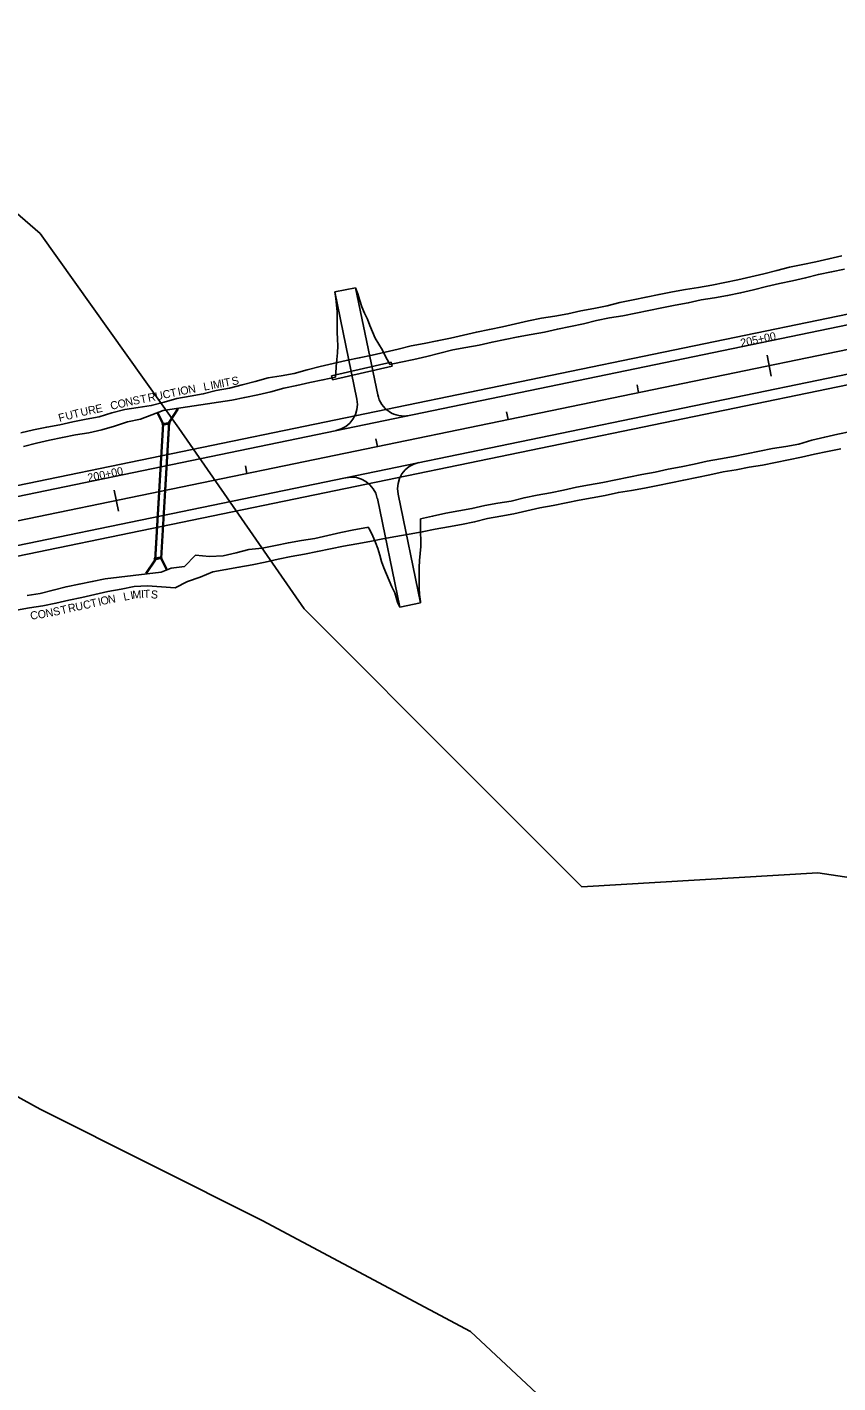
# Model space of a CAD drawing. Extents: x 979959 to 994833, y 1835619 to 1845316.
# Drawn here: x 985720 to 986328, y 1837353 to 1838370 of the extents above; entities that cross this region are included whole.
import ezdxf

# ---------------------------------------------------------------- set-up
doc = ezdxf.new("R2010")
doc.units = 0
for name, color, linetype in [('43', 7, 'Continuous'), ('Future 5 Lane Construction Limits', 7, 'Continuous'), ('R_Drainage', 7, 'Continuous'), ('R_Horz Alg', 7, 'Continuous'), ('R_Horz Alg Stationing', 7, 'Continuous'), ('R_Proposed Const Limits', 7, 'Continuous'), ('R_Proposed Road', 7, 'Continuous')]:
    doc.layers.add(name, color=color, linetype=linetype)

msp = doc.modelspace()

# ---------------------------------------------------------------- linework, layer by layer
at = {"layer": '43'}
for points in [[(985647.3, 1838286.1), (985729.8, 1838214.9), (985834, 1838069.1), (985927.8, 1837933.7), (986052.8, 1837808.6), (986136.1, 1837725.3), (986313.2, 1837735.7), (986521.5, 1837704.5)], [(986209, 1837246.1), (986052.8, 1837391.9), (985896.5, 1837475.2), (985729.8, 1837558.6), (985521.5, 1837673.2)]]:
    msp.add_lwpolyline(points, dxfattribs=at)
at = {"layer": 'Future 5 Lane Construction Limits'}
for points in [[(985715.3, 1838065.5), (985725, 1838067.8), (985734.8, 1838069.8), (985744.7, 1838071.6), (985754.5, 1838073.7), (985764.3, 1838075.7), (985774.1, 1838077.4), (985783.7, 1838080.5), (985793.4, 1838083), (985803.3, 1838084.5), (985813.2, 1838085.9), (985822.9, 1838088.6), (985832.5, 1838091.2), (985842.4, 1838093), (985852.2, 1838094.7), (985861.9, 1838097.2), (985871.8, 1838099), (985881.5, 1838101.4), (985891.1, 1838104.1), (985900.8, 1838106.7), (985910.7, 1838108.3), (985920.5, 1838110.1), (985930.2, 1838112.8), (985939.9, 1838115.2), (985949.6, 1838117.4), (985959.4, 1838119.7), (985969.2, 1838121.7), (985979, 1838123.8), (985988.7, 1838126.1), (985998.5, 1838128.3), (986008.2, 1838130.7), (986018, 1838132.5), (986027.8, 1838134.4), (986037.6, 1838136.5), (986047.4, 1838138.7), (986057.1, 1838141), (986066.9, 1838143.1), (986076.7, 1838145.1), (986086.4, 1838147.2), (986096.2, 1838149.5), (986106, 1838151.4), (986115.9, 1838153), (986125.8, 1838154.7), (986135.5, 1838156.9), (986145.3, 1838158.8), (986155.1, 1838160.8), (986164.8, 1838163.2), (986174.6, 1838165.2), (986184.4, 1838167.3), (986194.2, 1838169.3), (986204.1, 1838171.1), (986213.9, 1838172.9), (986223.8, 1838174.5), (986233.6, 1838176.3), (986243.4, 1838178.1), (986253.2, 1838180.3), (986263, 1838182.5), (986272.7, 1838184.6), (986282.4, 1838187.1), (986292.1, 1838189.6), (986301.9, 1838191.7), (986311.7, 1838193.8), (986321.5, 1838195.9), (986331.2, 1838198.1)], [(985712.1, 1837932.7), (985722, 1837934.3), (985731.9, 1837935.9), (985741.7, 1837937.8), (985751.4, 1837940.1), (985761.2, 1837942.1), (985770.9, 1837944.4), (985780.7, 1837946.7), (985790.6, 1837948.3), (985800.4, 1837950.3), (985810.5, 1837950.8), (985820.8, 1837950), (985831.2, 1837949.4), (985840.4, 1837954), (985849.9, 1837957.4), (985859.4, 1837961.3), (985869.2, 1837963), (985879, 1837964.8), (985888.9, 1837966.7), (985898.7, 1837968.6), (985908.4, 1837970.8), (985918.2, 1837972.8), (985928.1, 1837974.7), (985937.9, 1837976.7), (985947.7, 1837978.6), (985957.5, 1837980.5), (985967.3, 1837982.3), (985977.2, 1837984.1), (985987, 1837986), (985996.8, 1837987.8), (986006.7, 1837989.6), (986016.5, 1837991.3), (986026.3, 1837993.3), (986036.2, 1837995.1), (986046, 1837996.9), (986055.8, 1837998.8), (986065.5, 1838001.2), (986075.4, 1838003), (986085.2, 1838004.9), (986095, 1838007.1), (986104.7, 1838009.2), (986114.6, 1838011), (986124.4, 1838013), (986134.2, 1838015), (986144, 1838016.8), (986153.8, 1838018.6), (986163.6, 1838020.8), (986173.5, 1838022.4), (986183.3, 1838024.1), (986193.2, 1838026.1), (986203, 1838028.1), (986212.7, 1838030.1), (986222.5, 1838032.1), (986232.3, 1838034.1), (986242.1, 1838036.2), (986252, 1838037.9), (986261.8, 1838039.8), (986271.7, 1838041.3), (986281.5, 1838043.3), (986291.3, 1838045.3), (986301.1, 1838047.4), (986310.8, 1838049.5), (986320.6, 1838051.6), (986330.4, 1838053.6)]]:
    msp.add_lwpolyline(points, dxfattribs=at)
at = {"layer": 'R_Drainage'}
for p, q in [((985948.4, 1838108.2), (985993.3, 1838118.4)), ((985949.1, 1838105.2), (985993.9, 1838115.5)), ((985993.3, 1838118.4), (985993.9, 1838115.5)), ((985948.4, 1838108.2), (985949.1, 1838105.2)), ((985826.3, 1838073.4), (985833, 1838083.6)), ((985826.8, 1838073.3), (985833.4, 1838083.3)), ((985833.4, 1838083.3), (985833, 1838083.6)), ((985821.8, 1838072.2), (985815.8, 1837970.4)), ((985822.3, 1838072.3), (985816.3, 1837970.2)), ((985817.8, 1838080.1), (985818.3, 1838080.3)), ((985821.8, 1838072.2), (985817.8, 1838080.1)), ((985822.3, 1838072.3), (985818.3, 1838080.3)), ((985826.3, 1838073.4), (985820.4, 1837971.4)), ((985826.8, 1838073.3), (985820.9, 1837971.5)), ((985821.5, 1838072.2), (985827.1, 1838073.3)), ((985821.7, 1838071.2), (985821.5, 1838072.2)), ((985821.7, 1838071.2), (985827.3, 1838072.4)), ((985821.7, 1838071.2), (985826.8, 1838072.3)), ((985827.3, 1838072.4), (985827.1, 1838073.3)), ((985815.8, 1837970.4), (985809.2, 1837960.4)), ((985816.3, 1837970.2), (985809.6, 1837960.1)), ((985815.4, 1837971.3), (985821, 1837972.5)), ((985815.4, 1837971.3), (985820.4, 1837972.4)), ((985815.6, 1837970.4), (985815.4, 1837971.3)), ((985815.6, 1837970.4), (985821.2, 1837971.5)), ((985820.4, 1837971.4), (985824.4, 1837963.4)), ((985820.9, 1837971.5), (985824.8, 1837963.6)), ((985821.2, 1837971.5), (985821, 1837972.5)), ((985809.2, 1837960.4), (985809.6, 1837960.1)), ((985824.8, 1837963.6), (985824.4, 1837963.4))]:
    msp.add_line(p, q, dxfattribs=at)
at = {"layer": 'R_Horz Alg'}
msp.add_line((984572.5, 1837764), (990033.8, 1838891.5), dxfattribs=at)
at = {"layer": 'R_Horz Alg Stationing'}
for points in [[(986275.1, 1838123.7), (986278.3, 1838108)], [(986177.6, 1838101.5), (986178.8, 1838095.6)], [(986079.6, 1838081.3), (986080.9, 1838075.4)], [(985981.7, 1838061.1), (985982.9, 1838055.2)], [(985883.8, 1838040.9), (985885, 1838035)], [(985785.4, 1838022.6), (985788.7, 1838006.9)]]:
    msp.add_lwpolyline(points, dxfattribs=at)
at = {"layer": 'R_Proposed Const Limits'}
for points in [[(985992.2, 1838116.7), (986000.5, 1838118.5), (986010.3, 1838120.5), (986020, 1838122.8), (986029.7, 1838125.3), (986039.4, 1838127.7), (986049.2, 1838129.6), (986059.1, 1838131.3), (986068.9, 1838133.5), (986078.6, 1838135.6), (986088.5, 1838137.4), (986098.3, 1838139.3), (986108.1, 1838141.1), (986117.9, 1838143.3), (986127.7, 1838145.3), (986137.5, 1838147.3), (986147.2, 1838149.6), (986157, 1838151.6), (986166.9, 1838153.3), (986176.7, 1838155.3), (986186.5, 1838157.3), (986196.3, 1838159.3), (986206.1, 1838161.1), (986216, 1838162.9), (986225.7, 1838165.1), (986235.6, 1838166.7), (986245.5, 1838168.4), (986255.3, 1838170.4), (986265, 1838172.8), (986274.7, 1838175.1), (986284.4, 1838177.4), (986294.2, 1838179.5), (986304, 1838181.7), (986313.7, 1838184.3), (986323.5, 1838186.1), (986333.2, 1838188.3)], [(985992.2, 1838116.7), (985991.4, 1838118.2), (985989, 1838122.8), (985986.6, 1838127.4), (985983.8, 1838132), (985981.2, 1838136.5), (985979.1, 1838141.2), (985977.2, 1838145.9), (985975.3, 1838150.6), (985973.2, 1838155.3), (985971.2, 1838160), (985969.7, 1838164.8), (985968.2, 1838169.6), (985966.5, 1838174.3)], [(985951.5, 1838107.3), (985951.7, 1838110), (985951.9, 1838115.2), (985952.4, 1838120.4), (985952.8, 1838125.6), (985953.1, 1838130.7), (985952.9, 1838135.8), (985952.7, 1838140.9), (985952.6, 1838145.9), (985952.7, 1838151.1), (985952.7, 1838156.2), (985952.2, 1838161.2), (985951.6, 1838166.2), (985950.8, 1838171.1)], [(985717.4, 1838055.3), (985727.1, 1838057.7), (985736.9, 1838060), (985746.6, 1838062.1), (985756.5, 1838064), (985766.3, 1838065.6), (985776.1, 1838067.8), (985785.7, 1838070.6), (985795.3, 1838073.7), (985805.1, 1838075.8), (985822.1, 1838082.2), (985873.6, 1838089.9), (985883.4, 1838092.1), (985893.2, 1838094.1), (985903, 1838096.3), (985912.6, 1838098.9), (985922.4, 1838101.1), (985932.2, 1838103.2), (985942, 1838105.2), (985951.5, 1838107.3)], [(986015.2, 1838001.1), (986024.3, 1838003), (986034.1, 1838005.3), (986043.9, 1838007), (986053.8, 1838008.8), (986063.5, 1838011.1), (986073.3, 1838012.9), (986083.2, 1838014.4), (986092.9, 1838016.9), (986102.8, 1838018.8), (986112.6, 1838020.6), (986122.4, 1838022.5), (986132.2, 1838024.7), (986142, 1838026.6), (986151.9, 1838028.2), (986161.7, 1838030.2), (986171.5, 1838032.2), (986181.3, 1838034.2), (986191.1, 1838036.1), (986200.9, 1838038.2), (986210.7, 1838040.1), (986220.5, 1838042.1), (986230.3, 1838044.2), (986240.1, 1838046), (986249.9, 1838047.9), (986259.7, 1838049.8), (986269.5, 1838051.9), (986279.3, 1838053.9), (986289.2, 1838055.2), (986299.1, 1838057.1), (986308.7, 1838060), (986318.4, 1838062.3), (986328.2, 1838064.4), (986338, 1838066.4)], [(986015.2, 1838001.1), (986015.2, 1838000.6), (986015.2, 1837995.5), (986015.3, 1837990.4), (986015.4, 1837985.3), (986015.4, 1837980.2), (986014.9, 1837975), (986014.4, 1837969.8), (986014.3, 1837964.7), (986014.3, 1837959.6), (986014.2, 1837954.5), (986014.2, 1837949.3), (986014.5, 1837944.3), (986015.3, 1837939.1), (986015.3, 1837938)], [(985828.2, 1837964), (985838.1, 1837965.4), (985846.5, 1837973.8), (985857, 1837972.8), (985867.1, 1837973.3), (985876.8, 1837975.7), (985886.5, 1837978), (985896.5, 1837979.1), (985906.3, 1837981.1), (985916.1, 1837983.1), (985926, 1837984.9), (985935.9, 1837986.4), (985945.6, 1837988.5), (985955.4, 1837990.7), (985965.2, 1837992.7), (985975, 1837994.5), (985976, 1837994.7)], [(985976, 1837994.7), (985977.1, 1837992.7), (985979.4, 1837988.1), (985981.3, 1837983.4), (985983.1, 1837978.7), (985984.6, 1837973.9), (985986, 1837969.1), (985987.6, 1837964.3), (985989.6, 1837959.6), (985991.7, 1837954.9), (985993.8, 1837950.2), (985996, 1837945.6), (985997.9, 1837938.7), (985999.6, 1837934.9)], [(985778.7, 1837956.2), (985820.7, 1837961), (985828.2, 1837964)], [(985720.1, 1837943.5), (985729.9, 1837945.2), (985739.6, 1837947.7), (985749.3, 1837950.1), (985759.1, 1837952.1), (985769, 1837954), (985778.7, 1837956.2)]]:
    msp.add_lwpolyline(points, dxfattribs=at)
at = {"layer": 'R_Proposed Road'}
for p, q in [((984567.2, 1837789.5), (990028.6, 1838916.9)), ((984568.8, 1837781.7), (990030.2, 1838909.1)), ((984576.1, 1837746.4), (990037.5, 1838873.9)), ((984577.7, 1837738.6), (990039.1, 1838866)), ((985950.8, 1838171.1), (985966.5, 1838174.3)), ((985983.1, 1838094), (985966.5, 1838174.3)), ((985967.4, 1838090.8), (985950.8, 1838171.1)), ((985999.6, 1837934.9), (985982.8, 1838016.4)), ((986015.3, 1837938), (985998.4, 1838019.6)), ((985999.6, 1837934.9), (986015.3, 1837938))]:
    msp.add_line(p, q, dxfattribs=at)
for centre, start, end in [((986002.7, 1838098.1), 191.6644, 281.6644), ((985947.8, 1838086.8), 281.6644, 11.6644), ((986018, 1838023.7), 101.6644, 191.6644), ((985963.2, 1838012.3), 11.6644, 101.6644)]:
    msp.add_arc(centre, 20, start, end, dxfattribs=at)

# ---------------------------------------------------------------- texts
at = {"layer": 'Future 5 Lane Construction Limits'}
for s, rotation, p in [('N', 10.5552, (985841.4, 1838094.9)), ('L', 10.5552, (985852.9, 1838097.1)), ('I', 10.8926, (985858.2, 1838098)), ('M', 10.8926, (985860.1, 1838098.4)), ('I', 10.9749, (985866.4, 1838099.6)), ('T', 10.8302, (985868.4, 1838100)), ('S', 10.8302, (985874.1, 1838101.1)), ('N', 12.562, (985794.4, 1838085.2)), ('S', 11.4626, (985799.9, 1838086.4)), ('T', 11.4626, (985805.5, 1838087.5)), ('R', 11.4198, (985811.2, 1838088.7)), ('U', 11.4198, (985816.8, 1838089.8)), ('C', 11.471, (985822.4, 1838091)), ('T', 12.2203, (985828, 1838092.1)), ('I', 12.2203, (985833.7, 1838093.3)), ('O', 12.2203, (985835.7, 1838093.7)), ('U', 14.2158, (985749.6, 1838075)), ('T', 14.2158, (985755.2, 1838076.4)), ('U', 12.2951, (985760.8, 1838077.9)), ('R', 12.2951, (985766.5, 1838079.1)), ('E', 11.9819, (985772, 1838080.3)), ('C', 12.3558, (985783.2, 1838082.7)), ('O', 12.562, (985788.7, 1838083.9)), ('F', 14.5611, (985744.4, 1838073.6)), ('U', 11.4216, (985756.9, 1837932)), ('C', 13.3007, (985762.8, 1837933.2)), ('T', 13.3007, (985768.3, 1837934.5)), ('I', 13.222, (985774, 1837935.8)), ('O', 13.222, (985775.9, 1837936.3)), ('N', 9.4839, (985781.2, 1837937.6)), ('L', 11.5869, (985792.9, 1837939.6)), ('I', 11.5869, (985798.2, 1837940.7)), ('M', 3.0261, (985799.2, 1837941.2)), ('I', 3.0261, (985805.7, 1837941.6)), ('T', 3.0261, (985807.6, 1837941.7)), ('S', 355.3062, (985812.7, 1837941.6)), ('C', 8.6808, (985722.9, 1837925.4)), ('O', 8.6808, (985728.5, 1837926.2)), ('N', 10.94, (985734.5, 1837927.2)), ('S', 10.94, (985740.1, 1837928.3)), ('T', 13.4553, (985745.9, 1837929.5)), ('R', 11.4216, (985751.4, 1837930.9))]:
    msp.add_text(s, height=6, rotation=rotation, dxfattribs=at).set_placement(p)
at = {"layer": 'R_Horz Alg Stationing'}
for s, p in [('205+00', (986255.8, 1838129.9)), ('200+00', (985766.1, 1838028.8))]:
    msp.add_text(s, height=6, rotation=11.6644, dxfattribs=at).set_placement(p)

doc.saveas('drawing.dxf')
